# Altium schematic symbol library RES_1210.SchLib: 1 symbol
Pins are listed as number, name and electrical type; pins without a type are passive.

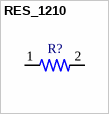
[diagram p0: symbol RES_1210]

## RES_1210
designator R?
1210 1%  0.5W; MP: 1-2176071-4
footprint RESC3126X65N
pins: 1, 2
